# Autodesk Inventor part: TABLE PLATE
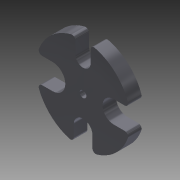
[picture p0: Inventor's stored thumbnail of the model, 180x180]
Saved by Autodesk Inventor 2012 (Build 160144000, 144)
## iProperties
Shininess: 64.0
Length Units: 11272
Angle Units: 11279
Time Units: 11290
Mass Units: 11286
Length Display Precision: 3
Angle Display Precision: 2
Compacted: True
Part Number: TABLE PLATE
Document SubType Name: Modeling
Created: 2003-11
Designer: Autodesk, Inc.
Manufacturer: Standard
Standards Organization: Custom
Mass: 435.491 g
Surface Area: 143.439 cm^2
Volume: 55.5473 cm^3
Density: 7.84 g/cm^3
Material: Steel, High Strength Low Alloy
Density: 0.0
Volumn: 0.0
Area: 0.0
PropertySet Name: Model Information
Control State: 0
Master: False
Checked Out: False
Author: Autodesk, Inc.
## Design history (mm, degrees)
sketch "Sketch1"
  geometry: C1 r 44.45 at (0, 0); 1 further point
  constraints: 1 centre point, 1 coincident
  dimensions: "d0" = 88.9 diameter of C1
extrude "Extrusion1" new body sketch "Sketch1" distance "d1" = 12.7; taper "d2" = 0 deg
sketch "Sketch2"
  geometry: L1 (-7.137, 43.873)-(-7.137, 28.575); L2 (7.137, 43.873)-(7.137, 28.575); L3 (0, 0)-(0, 40.794); L4 (0, 0)-(-21.298, 0); L5 (-8.725, -28.575)-(-8.725, -43.585); L6 (8.725, -28.575)-(8.725, -43.585); L7 (-28.575, 11.9)-(-42.828, 11.9); L8 (-28.575, -11.9)-(-42.828, -11.9); L9 (28.575, 10.312)-(43.237, 10.312); L10 (28.575, -10.312)-(43.237, -10.312); A1 r 7.137 centre (0, 28.575) between (-7.137, 28.575) and (7.137, 28.575); A2 r 8.725 centre (0, -28.575) between (8.725, -28.575) and (-8.725, -28.575); A3 r 11.9 centre (-28.575, 0) between (-28.575, -11.9) and (-28.575, 11.9); A4 r 10.312 centre (28.575, 0) between (28.575, 10.312) and (28.575, -10.312); A5 r 28.575 centre (0, 0) between (0, 28.575) and (28.575, 0)
  constraints: 20 end point, 11 point on circle, 8 tangent, 5 centre point, 4 horizontal, 4 point on line, 3 parallel, 2 perpendicular, 1 coincident, 1 vertical, 9 other
  dimensions: "d3" = 14.2748 diameter of A1; "d4" = 28.575 distance of L3.start A1.centre; "d7" = 8.7249 radius of A2; "d8" = 28.575 distance of L3.start A2.centre; "d9" = 23.7998 diameter of A3; "d10" = 20.6248 diameter of A4
extrude "Extrusion2" cut sketch "Sketch2" stored distance "d5" = 12.7; taper "d6" = 0 deg
fillet "Fillet1" dims "d11" = 3.175
sketch "Sketch3"
  geometry: C1 r 3.175 at (0, 0); 1 further point
  constraints: 1 centre point, 1 coincident
  dimensions: "d12" = 6.35 diameter of C1
extrude "Extrusion3" cut sketch "Sketch3" stored distance "d13" = 12.7; taper "d14" = 0 deg
body "Solid1"
